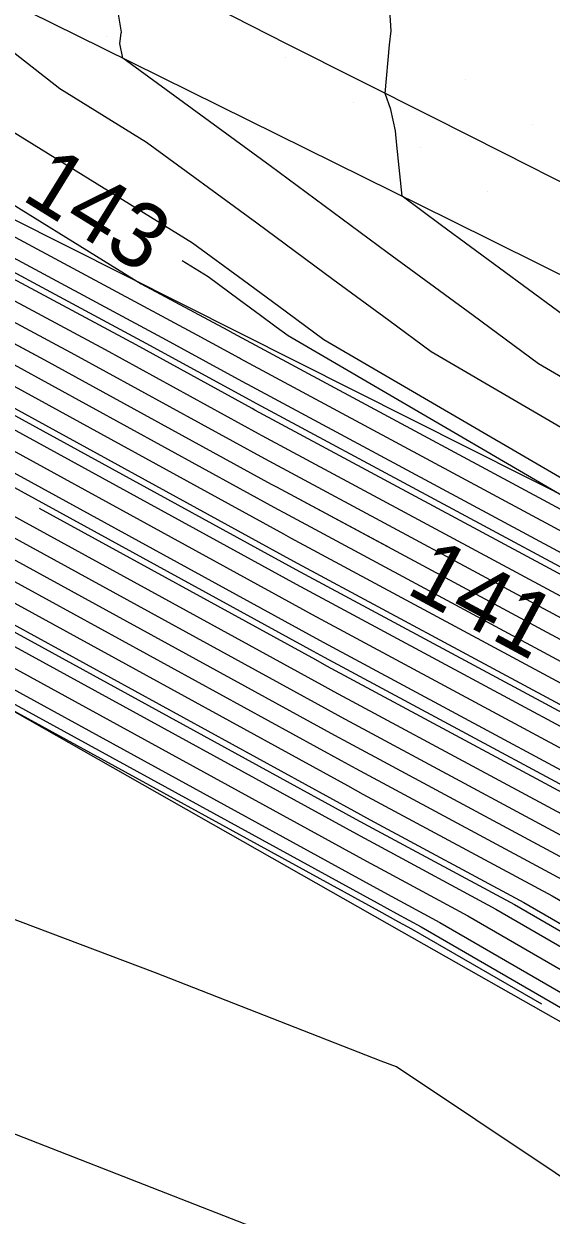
# Model space of a CAD drawing. Extents: x 2354170 to 2357230, y 866100 to 868290.
# Drawn here: x 2355104.52 to 2355120.82, y 867451.51 to 867488.33 of the extents above; entities that cross this region are included whole.
import ezdxf

# ---------------------------------------------------------------- set-up
doc = ezdxf.new("R2010")
doc.units = 0
for name, color, linetype in [('Default', 7, 'Continuous'), ('DTM Contours Major', 7, 'Continuous'), ('DTM Contours Minor', 7, 'Continuous'), ('DTM Contours Minor Text', 7, 'Continuous'), ('Exist DTM Breakline', 7, 'Continuous'), ('Exist DTM Scan Elevation Point', 7, 'Continuous'), ('Exist Roads EOP', 7, 'Continuous'), ('PH Exist DTM Breakline', 7, 'Continuous')]:
    doc.layers.add(name, color=color, linetype=linetype)

msp = doc.modelspace()

# ---------------------------------------------------------------- linework, layer by layer
at = {"layer": 'Default'}
for points in [[(2355152.49, 867449.764), (2355149.162, 867451.689), (2355139.515, 867457.648), (2355129.507, 867463.442), (2355112.774, 867472.437), (2355112.56, 867472.554), (2355103.265, 867477.646), (2355097.879, 867480.538), (2355088.526, 867485.764), (2355080.146, 867490.353), (2355061.522, 867500.481), (2355060.429, 867501.079), (2355056.695, 867503.109), (2355051.882, 867505.741), (2355040.285, 867511.911), (2355026.253, 867519.323), (2355025.557, 867520.149), (2355025.259, 867520.405), (2355024.823, 867520.774), (2355024.122, 867521.388), (2355022.753, 867522.587), (2355012.766, 867531.975), (2355009.539, 867534.688)], [(2355147.783, 867450.44), (2355140.068, 867455.205), (2355126.908, 867462.824), (2355113.442, 867470.063), (2355113.148, 867470.224), (2355100.43, 867477.191), (2355096.152, 867479.488), (2355088.722, 867483.639), (2355076.511, 867490.327), (2355061.926, 867498.259), (2355059.966, 867499.331), (2355057.031, 867500.926), (2355047.845, 867505.95), (2355038.564, 867510.887), (2355025.962, 867517.544), (2355024.829, 867518.124), (2355019.685, 867520.754), (2355004.941, 867530.263)], [(2355147.323, 867450.023), (2355140.252, 867454.391), (2355126.042, 867462.618), (2355113.665, 867469.271), (2355113.345, 867469.447), (2355099.485, 867477.039), (2355095.576, 867479.138), (2355088.787, 867482.931), (2355075.3, 867490.318), (2355062.061, 867497.518), (2355059.812, 867498.748), (2355057.143, 867500.199), (2355046.499, 867506.019), (2355037.991, 867510.546), (2355026.437, 867516.649), (2355024.891, 867517.44), (2355017.874, 867521.028), (2355004.42, 867529.705)], [(2355146.404, 867449.191), (2355140.621, 867452.763), (2355124.309, 867462.206), (2355114.11, 867467.689), (2355113.737, 867467.893), (2355097.596, 867476.735), (2355094.425, 867478.438), (2355088.917, 867481.515), (2355072.876, 867490.301), (2355062.33, 867496.036), (2355059.503, 867497.582), (2355057.367, 867498.744), (2355043.808, 867506.158), (2355036.844, 867509.863), (2355027.387, 867514.859), (2355025.015, 867516.072), (2355014.251, 867521.576), (2355003.378, 867528.588)], [(2355145.944, 867448.774), (2355140.805, 867451.948), (2355123.443, 867462), (2355114.333, 867466.897), (2355113.933, 867467.116), (2355096.651, 867476.584), (2355093.849, 867478.088), (2355088.983, 867480.807), (2355071.665, 867490.292), (2355062.464, 867495.295), (2355059.349, 867496.999), (2355057.478, 867498.016), (2355042.463, 867506.228), (2355036.27, 867509.522), (2355027.862, 867513.964), (2355025.078, 867515.388), (2355012.44, 867521.849), (2355002.857, 867528.03)], [(2355148.243, 867450.856), (2355139.884, 867456.019), (2355127.774, 867463.03), (2355113.22, 867470.854), (2355112.952, 867471.001), (2355101.375, 867477.343), (2355096.728, 867479.838), (2355088.656, 867484.347), (2355077.723, 867490.336), (2355061.791, 867499), (2355060.121, 867499.913), (2355056.919, 867501.654), (2355049.191, 867505.88), (2355039.138, 867511.228), (2355025.488, 867518.439), (2355024.767, 867518.808), (2355021.497, 867520.48), (2355011.48, 867526.94)], [(2354999.761, 867523.766), (2355025.512, 867510.599), (2355031.186, 867507.698), (2355032.255, 867507.133), (2355033.043, 867506.714), (2355058.261, 867492.923), (2355058.268, 867492.92), (2355058.958, 867492.542), (2355062.857, 867489.646), (2355063.618, 867489.086), (2355069.09, 867486.996), (2355089.439, 867475.85), (2355089.818, 867475.638), (2355090.036, 867475.521), (2355115.307, 867461.678), (2355115.891, 867461.358), (2355117.378, 867460.558), (2355142.095, 867446.249)], [(2355001.573, 867523.493), (2355025.45, 867511.283), (2355030.711, 867508.593), (2355032.829, 867507.474), (2355034.389, 867506.645), (2355058.15, 867493.651), (2355058.423, 867493.502), (2355063.272, 867490.851), (2355064.395, 867490.24), (2355089.374, 867476.558), (2355090.394, 867475.988), (2355090.981, 867475.673), (2355115.111, 867462.455), (2355115.668, 867462.149), (2355118.245, 867460.764), (2355141.911, 867447.063)], [(2355003.384, 867523.219), (2355025.388, 867511.967), (2355030.236, 867509.488), (2355033.402, 867507.816), (2355035.734, 867506.575), (2355058.038, 867494.378), (2355058.577, 867494.085), (2355063.137, 867491.591), (2355065.607, 867490.248), (2355089.309, 867477.266), (2355090.97, 867476.338), (2355091.926, 867475.825), (2355114.915, 867463.232), (2355115.446, 867462.941), (2355119.111, 867460.97), (2355141.726, 867447.877)], [(2355030.524, 867523.106), (2355032.625, 867521.309), (2355038.795, 867513.986), (2355041.432, 867512.593), (2355054.573, 867505.602), (2355056.472, 867504.564), (2355060.738, 867502.245), (2355061.253, 867501.963), (2355082.569, 867490.371), (2355088.396, 867487.18), (2355099.031, 867481.238), (2355105.155, 867477.95), (2355112.167, 867474.108), (2355112.329, 867474.019), (2355115.821, 867472.142)], [(2355007.006, 867522.671), (2355025.264, 867513.335), (2355029.286, 867511.278), (2355034.549, 867508.498), (2355038.426, 867506.436), (2355057.814, 867495.834), (2355058.886, 867495.251), (2355062.868, 867493.073), (2355068.03, 867490.266), (2355089.178, 867478.683), (2355092.121, 867477.038), (2355093.816, 867476.128), (2355114.522, 867464.785), (2355115.001, 867464.523), (2355120.844, 867461.382), (2355141.358, 867449.506)], [(2355008.818, 867522.397), (2355025.202, 867514.019), (2355028.812, 867512.174), (2355035.123, 867508.839), (2355039.771, 867506.367), (2355057.702, 867496.561), (2355059.04, 867495.834), (2355062.733, 867493.814), (2355069.242, 867490.275), (2355089.113, 867479.391), (2355092.697, 867477.388), (2355094.761, 867476.28), (2355114.326, 867465.562), (2355114.778, 867465.315), (2355121.71, 867461.588), (2355141.174, 867450.32)], [(2355133.326, 867464.748), (2355111.661, 867476.393), (2355111.579, 867476.439), (2355107.99, 867478.405), (2355100.758, 867482.288), (2355088.2, 867489.304), (2355086.204, 867490.397), (2355072.868, 867497.65), (2355066.703, 867502.56), (2355065.749, 867503.362), (2355064.445, 867504.473), (2355062.504, 867506.108), (2355060.837, 867507.469), (2355057.956, 867509.877), (2355053.375, 867514.001), (2355053.37, 867514.197), (2355053.354, 867514.482), (2355053.326, 867515.334), (2355053.121, 867517.443), (2355053.159, 867518.156), (2355053.261, 867518.489), (2355053.405, 867519.684)], [(2355206.008, 867399.059), (2355189.238, 867406.695), (2355183.856, 867411.301), (2355180.367, 867413.581), (2355176.811, 867415.677), (2355162.994, 867424.674), (2355150.813, 867431.854), (2355146.001, 867435.425), (2355142.145, 867438.036), (2355133.228, 867444.605), (2355116.039, 867456.096), (2355115.566, 867456.273), (2355108.587, 867458.998), (2355091.507, 867465.444), (2355074.831, 867472.029), (2355066.453, 867475.23), (2355056.492, 867482.561), (2355054.949, 867483.707), (2355041.295, 867493.758), (2355030.106, 867502.097), (2355027.412, 867502.954), (2355023.898, 867504.427), (2355002.064, 867511.013)], [(2355115.558, 867449.59), (2355097.876, 867456.495), (2355092.947, 867458.355), (2355078.344, 867464.121), (2355067.397, 867469.793), (2355054.41, 867478.207), (2355053.309, 867479.018), (2355053.269, 867479.047), (2355032.699, 867494.191), (2355028.51, 867497.313), (2355023.066, 867499.044), (2355022.365, 867499.338), (2355018.011, 867500.651), (2354998.598, 867510.504)], [(2355126.691, 867459.412), (2355122.576, 867461.794), (2355114.555, 867466.106), (2355114.13, 867466.339), (2355095.706, 867476.432), (2355093.273, 867477.738), (2355089.048, 867480.099), (2355070.453, 867490.283), (2355062.599, 867494.555), (2355059.194, 867496.416), (2355057.59, 867497.289), (2355041.117, 867506.297), (2355038.979, 867507.435)], [(2355120.528, 867458.027), (2355116.512, 867460.352), (2355116.114, 867460.567), (2355115.503, 867460.901), (2355103.575, 867467.435), (2355090.067, 867472.533), (2355085.228, 867474.444), (2355065.036, 867482.158), (2355059.674, 867486.103), (2355056.628, 867488.366), (2355049.891, 867493.326), (2355033.424, 867505.598)], [(2355153.083, 867451.468), (2355150.542, 867452.938), (2355138.963, 867460.09), (2355132.106, 867464.06), (2355112.107, 867474.811), (2355111.971, 867474.885), (2355106.1, 867478.101), (2355099.607, 867481.588), (2355088.33, 867487.888), (2355083.781, 867490.38), (2355061.119, 867502.704)], [(2355160.049, 867448.938), (2355153.28, 867452.036), (2355151.002, 867453.355), (2355138.778, 867460.905), (2355132.972, 867464.266), (2355111.884, 867475.602), (2355111.775, 867475.662), (2355107.045, 867478.253), (2355100.182, 867481.938), (2355088.265, 867488.596), (2355084.993, 867490.388), (2355063.123, 867502.281)], [(2355161.161, 867449.746), (2355153.675, 867453.172), (2355151.921, 867454.187), (2355138.41, 867462.533), (2355134.705, 867464.678), (2355111.439, 867477.185), (2355111.382, 867477.216), (2355108.934, 867478.557), (2355101.334, 867482.638), (2355088.135, 867490.012), (2355087.416, 867490.406), (2355082.612, 867493.018), (2355071.38, 867501.964)], [(2355161.717, 867450.15), (2355153.873, 867453.741), (2355152.381, 867454.604), (2355138.226, 867463.347), (2355135.571, 867464.884), (2355111.216, 867477.976), (2355111.186, 867477.993), (2355109.879, 867478.709), (2355101.91, 867482.987), (2355093.566, 867487.649), (2355089.223, 867490.754), (2355088.579, 867491.312), (2355087.503, 867492.168), (2355085.395, 867493.932), (2355076.057, 867501.368)], [(2355061.388, 867501.222), (2355081.358, 867490.362), (2355088.461, 867486.472), (2355098.455, 867480.888), (2355104.21, 867477.798), (2355112.364, 867473.331), (2355112.552, 867473.228), (2355130.373, 867463.648), (2355139.331, 867458.462), (2355149.622, 867452.105), (2355152.688, 867450.332)], [(2355091.798, 867491.54), (2355101.404, 867484.672), (2355102.23, 867484.042), (2355102.747, 867483.636), (2355108.147, 867480.298), (2355110.824, 867478.86), (2355110.99, 867478.77), (2355110.994, 867478.767), (2355136.437, 867465.09), (2355138.042, 867464.161), (2355152.841, 867455.02), (2355154.07, 867454.309)], [(2355138.391, 867464.646), (2355137.857, 867464.975), (2355137.304, 867465.296), (2355127.541, 867470.544), (2355113.796, 867478.566), (2355113.19, 867479.012), (2355112.397, 867479.596), (2355111.311, 867480.397), (2355109.738, 867481.549), (2355104.19, 867484.979), (2355101.955, 867486.732), (2355098.384, 867489.457)], [(2355129.361, 867474.176), (2355123.742, 867477.455), (2355121.009, 867479.466), (2355117.433, 867482.102), (2355116.212, 867483.002), (2355116.051, 867484.584), (2355116.011, 867485.027), (2355115.859, 867485.686), (2355115.691, 867486.18), (2355115.823, 867487.686), (2355115.87, 867488.118), (2355115.775, 867489.727)], [(2355153.76, 867455.853), (2355140.339, 867464.143), (2355138.651, 867465.467), (2355138.315, 867465.69), (2355137.894, 867465.965), (2355137.356, 867466.322), (2355136.636, 867466.801), (2355117.111, 867478.196), (2355115.796, 867479.163), (2355114.075, 867480.431), (2355111.721, 867482.168), (2355108.308, 867484.668), (2355105.633, 867486.322), (2355101.68, 867489.423)], [(2355154.22, 867456.269), (2355145.791, 867461.476), (2355140.534, 867465.6), (2355139.489, 867466.294), (2355138.177, 867467.151), (2355136.502, 867468.263), (2355134.261, 867469.752), (2355120.427, 867477.826), (2355118.403, 867479.315), (2355115.754, 867481.266), (2355112.13, 867483.94), (2355107.579, 867487.273), (2355107.491, 867487.729), (2355107.528, 867488.047), (2355107.536, 867488.076), (2355107.447, 867488.636)], [(2355171.176, 867438.625), (2355169.953, 867439.437), (2355157.319, 867446.883), (2355157.268, 867446.918), (2355152.293, 867449.195), (2355148.703, 867451.273), (2355139.7, 867456.834), (2355128.641, 867463.236), (2355112.997, 867471.645), (2355112.756, 867471.778), (2355102.32, 867477.494), (2355097.303, 867480.188), (2355088.591, 867485.055), (2355084.016, 867487.561)], [(2355191.614, 867423.483), (2355190.649, 867424.049), (2355186.174, 867426.303), (2355180.236, 867429.803), (2355171.523, 867435.586), (2355155.08, 867445.277), (2355155.044, 867445.302), (2355151.503, 867446.923), (2355146.864, 867449.607), (2355140.437, 867453.577), (2355125.175, 867462.412), (2355113.888, 867468.48), (2355113.541, 867468.67), (2355105.002, 867473.348)], [(2355101.926, 867471.016), (2355114.718, 867464.009), (2355115.223, 867463.732), (2355119.977, 867461.176), (2355141.542, 867448.692), (2355144.105, 867447.109), (2355150.318, 867443.514), (2355151.707, 867442.878), (2355151.721, 867442.868), (2355173.879, 867429.809), (2355177.296, 867427.541), (2355184.815, 867423.109), (2355186.57, 867422.225), (2355188.531, 867421.074)]]:
    msp.add_lwpolyline(points, dxfattribs=at)
at = {"layer": 'DTM Contours Major'}
msp.add_lwpolyline([(2355184.473, 867429.747), (2355182.033, 867431.185), (2355170.084, 867439.116), (2355157.133, 867446.75), (2355157.083, 867446.783), (2355152.227, 867449.006), (2355148.549, 867451.134), (2355139.761, 867456.562), (2355128.352, 867463.168), (2355113.071, 867471.382), (2355112.821, 867471.519), (2355102.005, 867477.444), (2355097.896, 867479.65)], dxfattribs=at)
at = {"layer": 'DTM Contours Minor'}
for points in [[(2354971.832, 867530.042), (2354980.053, 867524.895), (2354992.242, 867523.274), (2354998.573, 867522.062), (2355012.182, 867516.981), (2355025.554, 867510.143), (2355031.502, 867507.101), (2355031.873, 867506.905), (2355032.146, 867506.76), (2355041.126, 867501.85), (2355052.757, 867493.182), (2355057.188, 867489.919), (2355060.735, 867487.284), (2355064.563, 867484.467), (2355088.693, 867475.249), (2355089.586, 867474.897), (2355092.08, 867473.956), (2355115.438, 867461.16), (2355116.039, 867460.83), (2355116.801, 867460.421), (2355142.218, 867445.706), (2355142.419, 867445.582), (2355149.295, 867441.604)], [(2355183.506, 867425.878), (2355178.766, 867428.672), (2355172.701, 867432.697), (2355153.401, 867444.073), (2355153.375, 867444.09), (2355150.911, 867445.218), (2355145.484, 867448.358), (2355140.989, 867451.134), (2355122.576, 867461.794), (2355114.555, 867466.106), (2355114.13, 867466.339), (2355095.706, 867476.432), (2355093.273, 867477.738), (2355089.048, 867480.099), (2355070.453, 867490.283), (2355062.599, 867494.555), (2355059.194, 867496.416), (2355057.59, 867497.289), (2355041.117, 867506.297), (2355035.697, 867509.181), (2355028.337, 867513.069), (2355025.14, 867514.703), (2355010.629, 867522.123), (2355008.889, 867523.245)], [(2355234.342, 867399.179), (2355230.639, 867401.272), (2355227.572, 867403.078), (2355210.363, 867412.55), (2355203.577, 867416.685), (2355203.079, 867416.988), (2355190.876, 867424.151), (2355186.25, 867426.48), (2355180.4, 867429.928), (2355171.393, 867435.907), (2355155.267, 867445.411), (2355155.229, 867445.437), (2355151.569, 867447.112), (2355147.017, 867449.746), (2355140.375, 867453.848), (2355125.464, 867462.481), (2355113.813, 867468.744), (2355113.476, 867468.929), (2355098.855, 867476.938), (2355095.192, 867478.905), (2355088.83, 867482.459), (2355074.492, 867490.312), (2355062.15, 867497.024), (2355060.506, 867497.923)], [(2355160.79, 867449.477), (2355153.544, 867452.794), (2355151.615, 867453.91), (2355138.533, 867461.99), (2355134.127, 867464.541), (2355111.587, 867476.657), (2355111.513, 867476.698), (2355108.305, 867478.456), (2355100.95, 867482.404), (2355088.178, 867489.54), (2355086.608, 867490.4), (2355076.116, 867496.106)], [(2355154.68, 867456.686), (2355151.243, 867458.809), (2355142.418, 867465.733), (2355140.663, 867466.899), (2355138.46, 867468.336), (2355135.649, 867470.203), (2355131.885, 867472.703), (2355123.742, 867477.455), (2355121.009, 867479.466), (2355117.433, 867482.102), (2355116.212, 867483.002), (2355116.051, 867484.584), (2355116.011, 867485.027), (2355115.859, 867485.686), (2355115.691, 867486.18), (2355115.823, 867487.686), (2355115.87, 867488.118), (2355115.775, 867489.727)], [(2355199.94, 867428.204), (2355189.27, 867433.578), (2355186.934, 867434.955), (2355166.159, 867448.744), (2355162.731, 867450.765), (2355162.644, 867450.823), (2355154.202, 867454.688), (2355153.147, 867455.298), (2355137.919, 867464.704), (2355137.015, 867465.227), (2355121.077, 867473.795), (2355112.691, 867478.689), (2355112.321, 867478.961), (2355111.837, 867479.318), (2355111.175, 867479.806), (2355110.215, 867480.509), (2355109.419, 867481.002)], [(2355083.859, 867480.7), (2355089.265, 867477.738), (2355091.354, 867476.572), (2355092.556, 867475.926), (2355114.784, 867463.75), (2355115.297, 867463.468), (2355119.689, 867461.108), (2355141.603, 867448.42), (2355143.952, 867446.97), (2355150.252, 867443.324), (2355151.521, 867442.744), (2355151.534, 867442.735), (2355174.009, 867429.488), (2355177.133, 867427.415), (2355184.74, 867422.931), (2355186.344, 867422.124), (2355202.033, 867412.915)], [(2355099.996, 867480.719), (2355105.155, 867477.95), (2355112.167, 867474.108), (2355112.329, 867474.019), (2355131.239, 867463.854), (2355139.147, 867459.276), (2355150.082, 867452.522), (2355152.885, 867450.9), (2355158.937, 867448.13), (2355158.999, 867448.088), (2355168.776, 867442.325), (2355183.667, 867432.442), (2355187.76, 867430.029), (2355195.408, 867426.177), (2355204.124, 867421.062), (2355204.968, 867420.547), (2355216.461, 867413.545), (2355229.434, 867406.404), (2355234.574, 867403.378), (2355249.58, 867394.893), (2355259.153, 867389.42), (2355259.2, 867389.394), (2355260.851, 867388.082), (2355272.307, 867379.614)]]:
    msp.add_lwpolyline(points, dxfattribs=at)
at = {"layer": 'Exist DTM Breakline'}
msp.add_lwpolyline([(2355155.125, 867466.42), (2355152.887, 867467.534), (2355150.649, 867468.649), (2355148.412, 867469.765), (2355146.175, 867470.88), (2355143.938, 867471.996), (2355141.701, 867473.113), (2355139.464, 867474.23), (2355137.228, 867475.349), (2355134.993, 867476.468), (2355132.758, 867477.587), (2355130.523, 867478.708), (2355128.289, 867479.831), (2355126.056, 867480.954), (2355123.823, 867482.079), (2355121.59, 867483.204), (2355119.358, 867484.33), (2355117.126, 867485.456), (2355114.894, 867486.582), (2355112.662, 867487.708), (2355110.429, 867488.833)], dxfattribs=at)
at = {"layer": 'Exist DTM Scan Elevation Point'}
for p, q in [((2355116.073, 867487.983), (2355116.073, 867487.983)), ((2355107.06, 867487.952), (2355107.06, 867487.952)), ((2355112.609, 867487.278), (2355112.609, 867487.278)), ((2355118.158, 867486.604), (2355118.158, 867486.604)), ((2355114.694, 867485.898), (2355114.694, 867485.898)), ((2355120.243, 867485.225), (2355120.243, 867485.225)), ((2355116.779, 867484.519), (2355116.779, 867484.519)), ((2355118.864, 867483.14), (2355118.864, 867483.14))]:
    msp.add_line(p, q, dxfattribs=at)
at = {"layer": 'Exist Roads EOP'}
msp.add_lwpolyline([(2355182.218, 867450.227), (2355176.85, 867452.906), (2355171.48, 867455.582), (2355166.108, 867458.256), (2355160.736, 867460.928), (2355155.363, 867463.598), (2355149.989, 867466.266), (2355144.614, 867468.933), (2355139.238, 867471.598), (2355133.862, 867474.262), (2355128.486, 867476.926), (2355123.109, 867479.588), (2355117.732, 867482.25), (2355112.354, 867484.911), (2355106.976, 867487.571), (2355101.598, 867490.231), (2355096.219, 867492.889), (2355090.839, 867495.546), (2355085.459, 867498.202), (2355080.078, 867500.856), (2355074.697, 867503.51)], dxfattribs=at)
at = {"layer": 'PH Exist DTM Breakline'}
for points in [[(2355280.46, 867391.235), (2355274.142, 867395.519), (2355265.394, 867401.62), (2355259.051, 867405.124), (2355247.649, 867410.373), (2355235.138, 867416.592), (2355206.737, 867431.244), (2355191.277, 867438.296), (2355164.634, 867452.269), (2355154.996, 867456.973), (2355137.76, 867465.404), (2355102.312, 867483.232), (2355088.098, 867490.411), (2355056.326, 867505.512), (2355041.697, 867512.751), (2355024.659, 867520.002), (2355005.016, 867530.343)], [(2354998.987, 867523.883), (2355031.67, 867506.785), (2355063.384, 867490.232), (2355116.195, 867460.277), (2355149.553, 867441.314), (2355183.938, 867421.048), (2355201.572, 867411.115), (2355224.818, 867398.158), (2355251.509, 867383.227), (2355269.376, 867369.298), (2355287.251, 867347.908), (2355294.287, 867327.619), (2355296.523, 867319.456), (2355299.911, 867295.631), (2355302.764, 867267.241), (2355304.13, 867236.824), (2355305.048, 867209.593), (2355306.062, 867178.614), (2355306.867, 867134.639), (2355307.678, 867102.256), (2355309.303, 867062.926), (2355310.069, 867028.808), (2355310.233, 866999.689)]]:
    msp.add_lwpolyline(points, dxfattribs=at)

# ---------------------------------------------------------------- texts
at = {"layer": 'Default'}
msp.add_text('141', height=2, rotation=331.7393, dxfattribs=at).set_placement((2355116.284, 867470.758))
at = {"layer": 'DTM Contours Minor Text'}
msp.add_text('143', height=2, rotation=328.2772, dxfattribs=at).set_placement((2355104.405, 867482.925))

doc.saveas('drawing.dxf')
